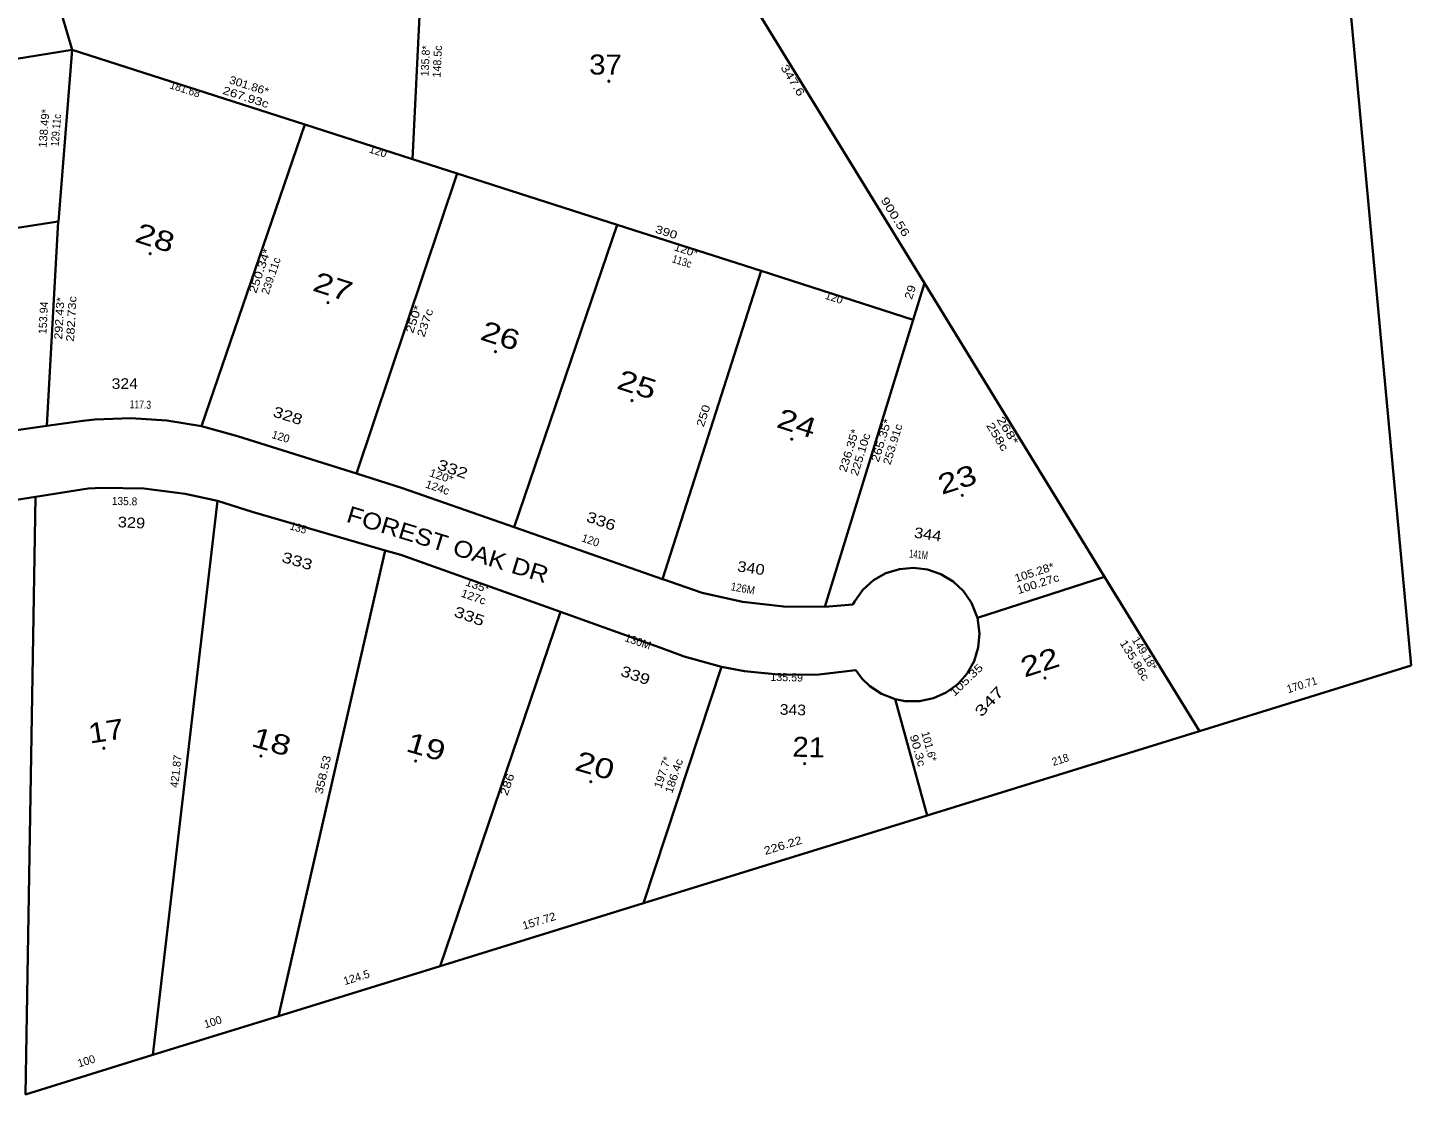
# Model space of a CAD drawing. Extents: x 2546959 to 2550387, y 581906 to 585027.
# Drawn here: x 2549237 to 2550274, y 582731 to 583531 of the extents above; entities that cross this region are included whole.
import ezdxf
from ezdxf.enums import TextEntityAlignment as Align

# ---------------------------------------------------------------- set-up
doc = ezdxf.new("R2010")
doc.units = 0
doc.header["$LTSCALE"] = 2.4
doc.header["$PDMODE"] = 32
doc.header["$PDSIZE"] = 1.2
for name, color, linetype in [('20', 7, 'Continuous'), ('38', 7, 'Continuous'), ('39', 7, 'Continuous'), ('41', 7, 'Continuous'), ('42', 7, 'Continuous')]:
    doc.layers.add(name, color=color, linetype=linetype)
doc.layers.add('40', color=7, linetype='Continuous', lineweight=35)

msp = doc.modelspace()

# ---------------------------------------------------------------- linework, layer by layer
at = {"layer": '40'}
for p, q in [((2550195.063, 583903.767), (2550273.96, 583052.222)), ((2549721.867, 583643.963), (2549908.935, 583339.07)), ((2549250.655, 583580.386), (2549270.052, 583514.047)), ((2549532.517, 583580.537), (2549525.145, 583432.101)), ((2549270.052, 583514.047), (2549259.813, 583385.34)), ((2549270.052, 583514.047), (2549444.587, 583457.98)), ((2549366.967, 583231.812), (2549444.587, 583457.98)), ((2549444.587, 583457.98), (2549525.145, 583432.101)), ((2549525.145, 583432.101), (2549558.818, 583421.284)), ((2549483.305, 583196.156), (2549558.818, 583421.284)), ((2549558.818, 583421.284), (2549678.628, 583382.798)), ((2549601.545, 583155.912), (2549678.628, 583382.798)), ((2549678.628, 583382.798), (2549786.52, 583348.139)), ((2549712.634, 583116.989), (2549786.52, 583348.139)), ((2549786.52, 583348.139), (2549900.478, 583311.531)), ((2549834.4, 583096.347), (2549900.478, 583311.531)), ((2549144.535, 583216.772), (2549251.093, 583231.95)), ((2549251.093, 583231.95), (2549278.029, 583235.786)), ((2549366.967, 583231.812), (2549393.953, 583224.388)), ((2549393.953, 583224.388), (2549483.305, 583196.156)), ((2549483.305, 583196.156), (2549517.683, 583185.295)), ((2549242.58, 583178.769), (2549282.074, 583184.911)), ((2549517.683, 583185.295), (2549601.545, 583155.912)), ((2549147.609, 583163.999), (2549242.58, 583178.769)), ((2549379.012, 583175.725), (2549405.098, 583167.535)), ((2549405.098, 583167.535), (2549504.655, 583138.594)), ((2549601.545, 583155.912), (2549712.634, 583116.989)), ((2549504.655, 583138.594), (2549424.797, 582789.354)), ((2549504.655, 583138.594), (2549516.438, 583135.169)), ((2549636.195, 583092.456), (2549516.438, 583135.169)), ((2549712.634, 583116.989), (2549712.837, 583116.919)), ((2549834.4, 583096.347), (2549855.37, 583098.124)), ((2549711.442, 583065.619), (2549636.195, 583092.456)), ((2549886.988, 583027), (2549910.993, 582939.862)), ((2549910.993, 582939.862), (2550115.103, 583003.046)), ((2549424.797, 582789.354), (2549546.008, 582826.877))]:
    msp.add_line(p, q, dxfattribs=at)
for points in [[(2549270.052, 583514.047), (2549058.121, 583479.818), (2549081.302, 583357.597), (2549259.719, 583385.325)], [(2549251.093, 583231.95), (2549259.719, 583385.325), (2549259.813, 583385.34)], [(2549900.478, 583311.531), (2549908.935, 583339.07), (2550044.053, 583118.847)], [(2549278.029, 583235.786), (2549287.01, 583236.77), (2549314.084, 583237.857), (2549341.125, 583236.138), (2549366.967, 583231.812)], [(2549282.074, 583184.911), (2549292.489, 583185.472), (2549323.766, 583184.946), (2549354.811, 583181.119), (2549379.012, 583175.725)], [(2549242.58, 583178.769), (2549235.186, 582730.658), (2549330.628, 582760.203)], [(2549379.012, 583175.725), (2549330.628, 582760.203), (2549424.797, 582789.354)], [(2549855.37, 583098.124), (2549856.9, 583100.624), (2549862.891, 583109.061), (2549870.816, 583116.146), (2549880.055, 583121.402), (2549890.194, 583124.594), (2549900.778, 583125.578), (2549911.332, 583124.31), (2549921.381, 583120.846), (2549930.476, 583115.342), (2549938.206, 583108.047), (2549944.226, 583099.286), (2549948.656, 583087.965)], [(2549948.656, 583087.965), (2550044.053, 583118.847), (2550115.103, 583003.046), (2550273.96, 583052.222)], [(2549712.837, 583116.919), (2549742.285, 583106.85), (2549772.648, 583100.02), (2549803.571, 583096.508), (2549834.4, 583096.347)], [(2549636.195, 583092.456), (2549546.008, 582826.877), (2549698.481, 582874.077)], [(2549948.656, 583087.965), (2549950.26, 583076.33), (2549949.326, 583065.742), (2549946.183, 583055.587), (2549940.971, 583046.323), (2549933.923, 583038.366), (2549925.358, 583032.072), (2549915.658, 583027.723), (2549905.259, 583025.517), (2549894.63, 583025.55), (2549886.988, 583027)], [(2549756.789, 583051.174), (2549728.855, 583058.979), (2549711.442, 583065.619)], [(2549756.789, 583051.174), (2549698.481, 582874.077), (2549910.993, 582939.862)], [(2549857.579, 583048.8), (2549829.825, 583045.53), (2549801.88, 583045.244), (2549774.065, 583047.943), (2549756.789, 583051.174)], [(2549886.988, 583027), (2549876.901, 583030.938), (2549868.05, 583036.825), (2549862.337, 583042.395), (2549857.579, 583048.8)]]:
    msp.add_lwpolyline(points, dxfattribs=at)
at = {"layer": '41'}
for p in [(2549672.416, 583490.476), (2549328.625, 583361.07), (2549461.892, 583324.373), (2549587.433, 583287.677), (2549689.798, 583250.98), (2549809.546, 583222.009), (2549937.339, 583179.935), (2549999.297, 583042.927), (2549293.859, 582990.237), (2549411.674, 582984.443), (2549527.559, 582980.58), (2549819.202, 582978.649), (2549658.895, 582965.129)]:
    msp.add_point(p, dxfattribs=at)

# ---------------------------------------------------------------- texts
at = {"layer": '20', "width": 1.15}
msp.add_text('FOREST OAK DR', height=12.5, rotation=342.806, dxfattribs=at).set_placement((2549549.837, 583137.059), align=Align.CENTER)
at = {"layer": '38', "width": 1.1}
msp.add_text('37', height=15, dxfattribs=at).set_placement((2549669.936, 583495.476), align=Align.CENTER)
at = {"layer": '38'}
for s, rotation, width, p in [('28', 342.191, 1.3, (2549330.092, 583365.92)), ('27', 342.191, 1.3, (2549463.37, 583329.228)), ('26', 342.191, 1.3, (2549588.915, 583292.535)), ('25', 342.191, 1.3, (2549691.26, 583255.842)), ('24', 342.191, 1.3, (2549811.044, 583226.829)), ('23', 17.938, 1.3, (2549935.77, 583184.664)), ('22', 17.938, 1.3, (2549997.742, 583047.599)), ('17', 8.84, 1.2, (2549296.676, 582995.739)), ('18', 343.791, 1.3, (2549417.499, 582988.006)), ('19', 343.791, 1.3, (2549533.391, 582984.167)), ('21', 358.37, 1.1, (2549822.071, 582983.604)), ('20', 343.791, 1.3, (2549659.985, 582970.086))]:
    msp.add_text(s, height=15, rotation=rotation, dxfattribs=dict(at, width=width)).set_placement(p, align=Align.CENTER)
at = {"layer": '39'}
for s, rotation, width, p in [('324', 0.317, 1.1, (2549309.565, 583259.706)), ('328', 342.466, 1.25, (2549430.585, 583235.832)), ('332', 340.691, 1.3, (2549553.997, 583195.896)), ('329', 357.015, 1.15, (2549314.374, 583155.489)), ('336', 340.691, 1.25, (2549665.354, 583156.857)), ('344', 351.629, 1.15, (2549910.95, 583146.705)), ('333', 343.791, 1.3, (2549437.731, 583126.849)), ('340', 351.453, 1.15, (2549778.419, 583121.424)), ('335', 340.371, 1.3, (2549566.529, 583085.489)), ('339', 340.371, 1.25, (2549691.006, 583041.116)), ('347', 46.953, 1.45, (2549960.476, 583022.538)), ('343', 358.545, 1.1, (2549810.258, 583015.122))]:
    msp.add_text(s, height=8, rotation=rotation, dxfattribs=dict(at, width=width)).set_placement(p, align=Align.CENTER)
at = {"layer": '42'}
for s, rotation, p in [('135.8*', 87.159, (2549537.836, 583505.568)), ('148.5c', 87.159, (2549546.795, 583505.141)), ('120', 342.191, (2549498.55, 583435.107)), ('239.11c', 71.058, (2549421.942, 583343.562)), ('120', 342.191, (2549840.357, 583325.349)), ('153.94', 86.781, (2549251.441, 583312.859)), ('120', 342.961, (2549425.588, 583221.038)), ('120', 340.691, (2549657.749, 583143.359)), ('130M', 341.103, (2549693.268, 583067.418)), ('149.18*', 301.531, (2550071.523, 583059.654)), ('135.59', 358.545, (2549805.618, 583040.489)), ('101.6*', 285.402, (2549909.629, 582990.776)), ('421.87', 83.358, (2549350.845, 582972.598)), ('124.5', 17.201, (2549484.107, 582815.499)), ('100', 17.201, (2549376.429, 582782.113)), ('100', 17.2, (2549281.603, 582752.78))]:
    msp.add_text(s, height=5.999, rotation=rotation, dxfattribs=at).set_placement(p, align=Align.CENTER)
for s, rotation, width, p in [('347.6', 301.531, 1.3, (2549807.71, 583489.618)), ('301.86*', 342.191, 1.1, (2549401.8, 583484.349)), ('181.68', 342.191, 0.95, (2549353.819, 583481.622)), ('267.93c', 342.191, 1.25, (2549399.386, 583475.701)), ('138.49*', 85.452, 1.05, (2549252.025, 583454.831)), ('129.11c', 85.452, 0.85, (2549260.925, 583453.438)), ('900.56', 301.531, 1.35, (2549884.616, 583387.22)), ('390', 342.191, 1.25, (2549714.635, 583374.475)), ('120*', 342.191, 1.1, (2549729.425, 583360.975)), ('250.34*', 71.058, 1.25, (2549413.655, 583347.263)), ('113c', 342.191, 0.85, (2549726.293, 583352.557)), ('29', 72.929, 1.2, (2549901.133, 583331.371)), ('292.43*', 86.781, 1.15, (2549263.463, 583312.491)), ('282.73c', 86.781, 1.2, (2549272.422, 583312.064)), ('250*', 71.457, 1.3, (2549528.952, 583311.105)), ('237c', 71.457, 1.25, (2549537.485, 583308.331)), ('117.3', 358.341, 0.8, (2549321.142, 583244.978)), ('250', 72.274, 1.25, (2549746.053, 583238.679)), ('265.35*', 72.929, 1.2, (2549879.534, 583220.226)), ('253.91c', 72.929, 1.1, (2549888.062, 583217.305)), ('258c', 301.531, 1.35, (2549961.148, 583222.315)), ('268*', 301.531, 1.4, (2549968.827, 583227.007)), ('236.35*', 72.93, 1.2, (2549855.268, 583212.653)), ('225.10c', 72.93, 1.15, (2549863.796, 583209.731)), ('124c', 341.204, 1.05, (2549543.03, 583182.938)), ('120*', 341.204, 1.1, (2549545.91, 583191.471)), ('135.8', 358.722, 0.95, (2549309.307, 583172.54)), ('135', 343.536, 0.95, (2549438.813, 583152.672)), ('141M', 354.666, 0.7, (2549904.336, 583132.591)), ('105.28*', 17.938, 1.1, (2549992.229, 583119.316)), ('100.27c', 17.938, 1.15, (2549995.001, 583110.782)), ('127c', 340.371, 1.1, (2549570.018, 583100.901)), ('135*', 340.371, 1.1, (2549573.004, 583109.435)), ('126M', 349.39, 0.9, (2549772.345, 583107.164)), ('135.86c', 301.531, 1.2, (2550064.04, 583054.639)), ('105.35', 43.909, 1.25, (2549942.469, 583039.327)), ('170.71', 17.2, 0.95, (2550192.811, 583034.893)), ('90.3c', 285.402, 1.25, (2549901.189, 582987.701)), ('358.53', 77.12, 1.2, (2549460.972, 582969.666)), ('197.7*', 71.777, 1.05, (2549715.491, 582971.228)), ('218', 17.201, 0.95, (2550011.726, 582978.806)), ('186.4c', 71.777, 1.1, (2549724.024, 582968.455)), ('286', 71.243, 1.25, (2549599.034, 582962.094)), ('226.22', 17.2, 1.2, (2549803.77, 582914.49)), ('157.72', 17.201, 1.05, (2549620.959, 582857.845))]:
    msp.add_text(s, height=5.999, rotation=rotation, dxfattribs=dict(at, width=width)).set_placement(p, align=Align.CENTER)

doc.saveas('drawing.dxf')
